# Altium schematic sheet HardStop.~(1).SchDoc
size A
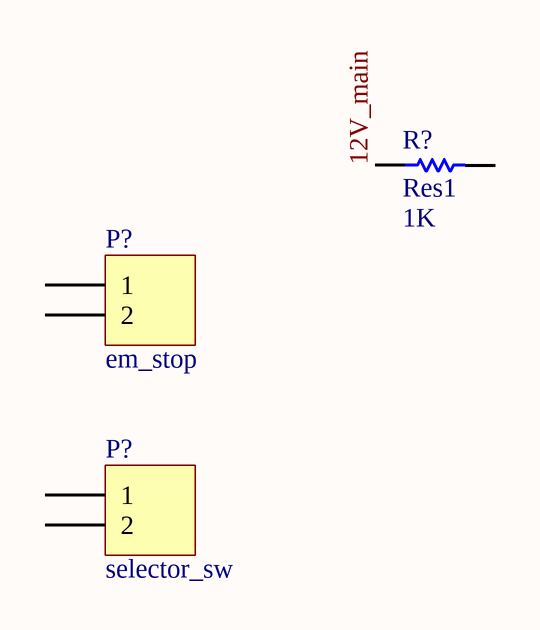
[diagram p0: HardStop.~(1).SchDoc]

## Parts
(Parts that share a designator on the sheet are numbered #1, #2 ... from top to bottom, then left to right.)
P?#1  em_stop  [HDR1X2H]
P?#2  selector_sw  [HDR1X2H]
R?  Res1  value 1K  [AXIAL-0.3]

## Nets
12V_main: R?.1

Not connected (* = marked no-connect by the designer): P?#1 1 2; P?#2 1 2; R? 2

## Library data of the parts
P?#1 P?#2 = Header 2H: Header, 2-Pin, Right Angle
R? = Res1: Resistor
